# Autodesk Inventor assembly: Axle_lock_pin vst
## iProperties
Shininess: 20.0
Length Units: 11269
Angle Units: 11279
Time Units: 11290
Mass Units: 11283
Length Display Precision: 3
Angle Display Precision: 2
Created: 2001-04
Part Number: Axle_lock_pin vst
Document SubType Name: Baugruppe
Designer: dl
Density: 0.0
Volumn: 0.0
Area: 0.0
PropertySet Name: Model Information
Control State: 0
Master: False
Checked Out: False
Author: dl
